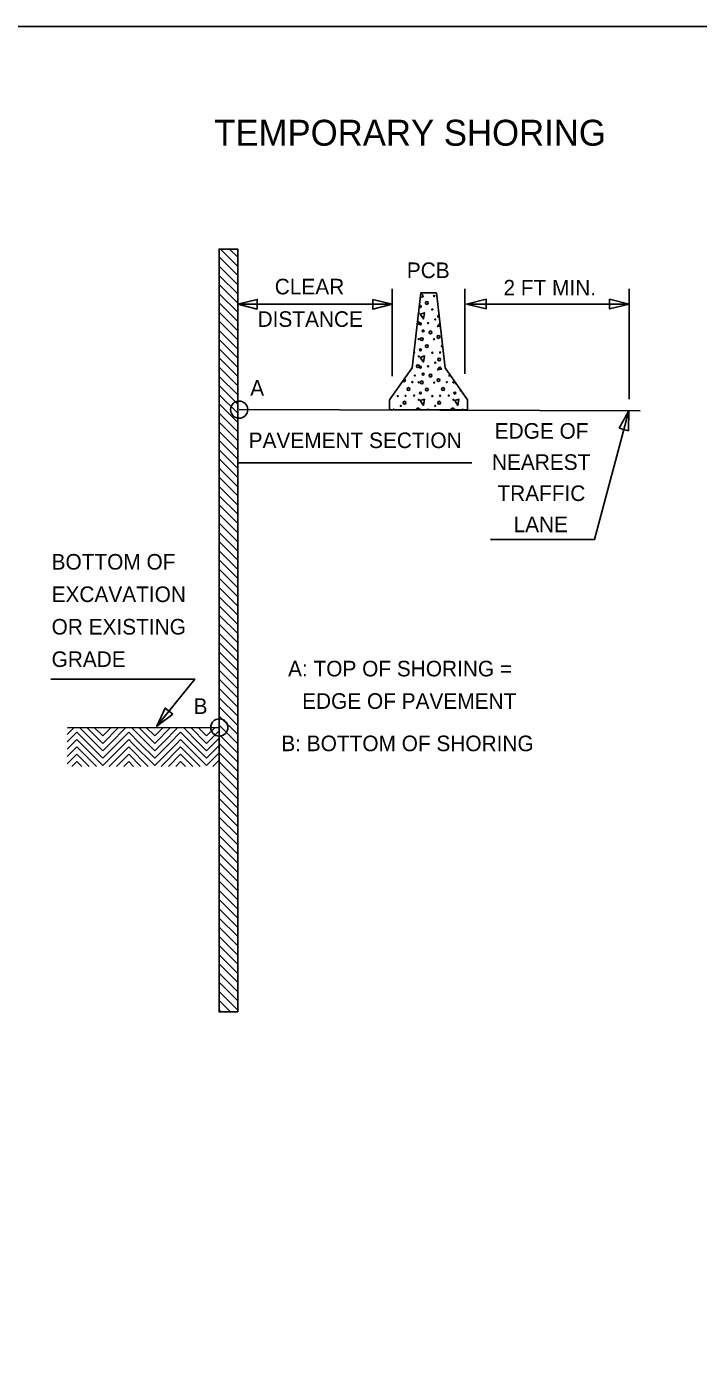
# Model space of a CAD drawing. Extents: x 2487012 to 2497594, y 369516 to 371986.
# Drawn here: x 2487672 to 2487943, y 370720 to 371258 of the extents above; entities that cross this region are included whole.
import ezdxf

# ---------------------------------------------------------------- set-up
doc = ezdxf.new("R2010")
doc.units = 0
for name, color, linetype in [('TC LABEL TEMP SHORING', 7, 'Continuous'), ('TC LABEL TEXT', 7, 'Continuous'), ('TC SHEET LAYOUT SHAPE', 7, 'Continuous')]:
    doc.layers.add(name, color=color, linetype=linetype)

msp = doc.modelspace()

# ---------------------------------------------------------------- linework, layer by layer
at = {"layer": 'TC LABEL TEMP SHORING'}
for p, q in [((2487757.21, 371161.32), (2487750.23, 371168.3)), ((2487757.21, 371165.03), (2487753.94, 371168.3)), ((2487757.21, 371157.61), (2487749.68, 371165.13)), ((2487757.21, 371153.89), (2487749.68, 371161.42)), ((2487757.21, 371150.18), (2487749.68, 371157.71)), ((2487757.21, 371146.47), (2487749.68, 371154)), ((2487757.21, 371142.76), (2487749.68, 371150.28)), ((2487819.64, 371117), (2487819.64, 371152.28)), ((2487849.06, 371117.94), (2487849.06, 371152.28)), ((2487915.46, 371107.65), (2487915.46, 371152.28)), ((2487757.21, 371139.04), (2487749.68, 371146.57)), ((2487757.21, 371135.33), (2487749.68, 371142.86)), ((2487757.21, 371131.62), (2487749.68, 371139.15)), ((2487757.21, 371127.91), (2487749.68, 371135.43)), ((2487838.99, 371138.15), (2487838.94, 371138.21)), ((2487757.21, 371124.19), (2487749.68, 371131.72)), ((2487757.21, 371120.48), (2487749.68, 371128.01)), ((2487757.21, 371116.77), (2487749.68, 371124.3)), ((2487757.21, 371113.06), (2487749.68, 371120.59)), ((2487757.21, 371109.35), (2487749.68, 371116.87)), ((2487757.21, 371105.63), (2487749.68, 371113.16)), ((2487757.21, 371101.92), (2487749.68, 371109.45)), ((2487818.64, 371107.25), (2487818.68, 371107.47)), ((2487757.21, 371098.21), (2487749.68, 371105.74)), ((2487757.21, 371094.5), (2487749.68, 371102.02)), ((2487919.88, 371102.9), (2487757.8, 371103.41)), ((2487757.21, 371090.78), (2487749.68, 371098.31)), ((2487757.21, 371087.07), (2487749.68, 371094.6)), ((2487757.21, 371083.36), (2487749.68, 371090.89)), ((2487757.21, 371079.65), (2487749.68, 371087.17)), ((2487757.21, 371075.93), (2487749.68, 371083.46)), ((2487757.46, 371081.86), (2487851.89, 371081.86)), ((2487757.21, 371072.22), (2487749.68, 371079.75)), ((2487757.21, 371068.51), (2487749.68, 371076.04)), ((2487757.21, 371064.8), (2487749.68, 371072.33)), ((2487757.21, 371061.09), (2487749.68, 371068.61)), ((2487757.21, 371057.37), (2487749.68, 371064.9)), ((2487757.21, 371053.66), (2487749.68, 371061.19)), ((2487757.21, 371049.95), (2487749.68, 371057.48)), ((2487757.21, 371046.24), (2487749.68, 371053.76)), ((2487757.21, 371042.52), (2487749.68, 371050.05)), ((2487757.21, 371038.81), (2487749.68, 371046.34)), ((2487757.21, 371035.1), (2487749.68, 371042.63)), ((2487757.21, 371031.39), (2487749.68, 371038.91)), ((2487757.21, 371027.67), (2487749.68, 371035.2)), ((2487757.21, 371023.96), (2487749.68, 371031.49)), ((2487757.21, 371020.25), (2487749.68, 371027.78)), ((2487757.21, 371016.54), (2487749.68, 371024.07)), ((2487757.21, 371012.83), (2487749.68, 371020.35)), ((2487757.21, 371009.11), (2487749.68, 371016.64)), ((2487757.21, 371005.4), (2487749.68, 371012.93)), ((2487757.21, 371001.69), (2487749.68, 371009.22)), ((2487757.21, 370997.98), (2487749.68, 371005.5)), ((2487757.21, 370994.26), (2487749.68, 371001.79)), ((2487757.21, 370990.55), (2487749.68, 370998.08)), ((2487757.21, 370986.84), (2487749.68, 370994.37)), ((2487757.21, 370983.13), (2487749.68, 370990.65)), ((2487757.21, 370979.41), (2487749.68, 370986.94)), ((2487757.21, 370975.7), (2487749.68, 370983.23)), ((2487757.21, 370971.99), (2487749.68, 370979.52)), ((2487688.25, 370972.11), (2487691.05, 370974.91)), ((2487688.25, 370969.14), (2487692.15, 370973.04)), ((2487688.34, 370974.74), (2487749.77, 370974.91)), ((2487696.71, 370968.48), (2487692.15, 370973.04)), ((2487699.68, 370968.48), (2487693.24, 370974.91)), ((2487702.65, 370968.48), (2487696.21, 370974.91)), ((2487702.65, 370971.45), (2487699.18, 370974.91)), ((2487702.65, 370968.48), (2487709.08, 370974.91)), ((2487702.65, 370971.45), (2487706.11, 370974.91)), ((2487705.62, 370968.48), (2487712.05, 370974.91)), ((2487708.59, 370968.48), (2487713.15, 370973.04)), ((2487717.71, 370968.48), (2487713.15, 370973.04)), ((2487720.68, 370968.48), (2487714.24, 370974.91)), ((2487723.65, 370968.48), (2487717.21, 370974.91)), ((2487723.65, 370971.45), (2487720.18, 370974.91)), ((2487723.65, 370968.48), (2487730.08, 370974.91)), ((2487723.65, 370971.45), (2487727.11, 370974.91)), ((2487726.62, 370968.48), (2487733.05, 370974.91)), ((2487729.59, 370968.48), (2487734.15, 370973.04)), ((2487738.71, 370968.48), (2487734.15, 370973.04)), ((2487741.68, 370968.48), (2487735.24, 370974.91)), ((2487744.65, 370968.48), (2487738.21, 370974.91)), ((2487744.65, 370971.45), (2487741.18, 370974.91)), ((2487744.65, 370971.45), (2487748.11, 370974.91)), ((2487744.65, 370968.48), (2487749.77, 370973.6)), ((2487757.21, 370968.28), (2487749.68, 370975.81)), ((2487688.25, 370966.17), (2487690.55, 370968.48)), ((2487690.55, 370968.48), (2487692.15, 370970.07)), ((2487693.74, 370968.48), (2487692.15, 370970.07)), ((2487702.65, 370959.57), (2487693.74, 370968.48)), ((2487702.65, 370962.54), (2487696.71, 370968.48)), ((2487702.65, 370965.51), (2487699.68, 370968.48)), ((2487702.65, 370959.57), (2487711.55, 370968.48)), ((2487702.65, 370962.54), (2487708.59, 370968.48)), ((2487702.65, 370965.51), (2487705.62, 370968.48)), ((2487711.55, 370968.48), (2487713.15, 370970.07)), ((2487714.74, 370968.48), (2487713.15, 370970.07)), ((2487723.65, 370959.57), (2487714.74, 370968.48)), ((2487723.65, 370962.54), (2487717.71, 370968.48)), ((2487723.65, 370965.51), (2487720.68, 370968.48)), ((2487723.65, 370959.57), (2487732.55, 370968.48)), ((2487723.65, 370962.54), (2487729.59, 370968.48)), ((2487723.65, 370965.51), (2487726.62, 370968.48)), ((2487732.55, 370968.48), (2487734.15, 370970.07)), ((2487735.74, 370968.48), (2487734.15, 370970.07)), ((2487744.65, 370959.57), (2487735.74, 370968.48)), ((2487744.65, 370962.54), (2487738.71, 370968.48)), ((2487744.65, 370965.51), (2487741.68, 370968.48)), ((2487744.65, 370965.51), (2487747.62, 370968.48)), ((2487744.65, 370962.54), (2487749.77, 370967.66)), ((2487747.62, 370968.48), (2487749.77, 370970.63)), ((2487757.21, 370964.57), (2487749.68, 370972.09)), ((2487757.21, 370960.85), (2487749.68, 370968.38)), ((2487688.25, 370963.2), (2487692.15, 370967.1)), ((2487688.25, 370960.23), (2487692.15, 370964.13)), ((2487700.08, 370959.16), (2487692.15, 370967.1)), ((2487697.11, 370959.16), (2487692.15, 370964.13)), ((2487705.21, 370959.16), (2487713.15, 370967.1)), ((2487708.18, 370959.16), (2487713.15, 370964.13)), ((2487721.08, 370959.16), (2487713.15, 370967.1)), ((2487718.11, 370959.16), (2487713.15, 370964.13)), ((2487726.21, 370959.16), (2487734.15, 370967.1)), ((2487729.18, 370959.16), (2487734.15, 370964.13)), ((2487742.08, 370959.16), (2487734.15, 370967.1)), ((2487739.11, 370959.16), (2487734.15, 370964.13)), ((2487744.65, 370959.57), (2487749.77, 370964.69)), ((2487757.21, 370957.14), (2487749.68, 370964.67)), ((2487690.15, 370959.16), (2487692.15, 370961.16)), ((2487694.14, 370959.16), (2487692.15, 370961.16)), ((2487711.15, 370959.16), (2487713.15, 370961.16)), ((2487715.14, 370959.16), (2487713.15, 370961.16)), ((2487732.15, 370959.16), (2487734.15, 370961.16)), ((2487736.14, 370959.16), (2487734.15, 370961.16)), ((2487747.21, 370959.16), (2487749.77, 370961.72)), ((2487757.21, 370953.43), (2487749.68, 370960.96)), ((2487757.21, 370949.72), (2487749.68, 370957.24)), ((2487757.21, 370946), (2487749.68, 370953.53)), ((2487757.21, 370942.29), (2487749.68, 370949.82)), ((2487757.21, 370938.58), (2487749.68, 370946.11)), ((2487757.21, 370934.87), (2487749.68, 370942.39)), ((2487757.21, 370931.15), (2487749.68, 370938.68)), ((2487757.21, 370927.44), (2487749.68, 370934.97)), ((2487757.21, 370923.73), (2487749.68, 370931.26)), ((2487757.21, 370920.02), (2487749.68, 370927.55)), ((2487757.21, 370916.31), (2487749.68, 370923.83)), ((2487757.21, 370912.59), (2487749.68, 370920.12)), ((2487757.21, 370908.88), (2487749.68, 370916.41)), ((2487757.21, 370905.17), (2487749.68, 370912.7)), ((2487757.21, 370901.46), (2487749.68, 370908.98)), ((2487757.21, 370897.74), (2487749.68, 370905.27)), ((2487757.21, 370894.03), (2487749.68, 370901.56)), ((2487757.21, 370890.32), (2487749.68, 370897.85)), ((2487757.21, 370886.61), (2487749.68, 370894.13)), ((2487757.21, 370882.89), (2487749.68, 370890.42)), ((2487757.21, 370879.18), (2487749.68, 370886.71)), ((2487757.21, 370875.47), (2487749.68, 370883)), ((2487757.21, 370871.76), (2487749.68, 370879.29)), ((2487757.21, 370868.05), (2487749.68, 370875.57)), ((2487757.21, 370864.33), (2487749.68, 370871.86)), ((2487757.21, 370860.62), (2487749.68, 370868.15)), ((2487754.26, 370859.86), (2487749.68, 370864.44)), ((2487750.55, 370859.86), (2487749.68, 370860.72))]:
    msp.add_line(p, q, dxfattribs=at)
for points in [[(2487757.21, 370859.86), (2487749.68, 370859.86), (2487749.68, 371168.3), (2487757.21, 371168.3)], [(2487818.64, 371103.36), (2487850.15, 371103.36), (2487850.15, 371107.42), (2487841.04, 371120.26), (2487837.56, 371150.61), (2487831.23, 371150.61), (2487827.75, 371120.26), (2487818.64, 371107.42)], [(2487831.05, 371142.05), (2487832.29, 371140.12), (2487832.68, 371142.6)], [(2487831.05, 371124.55), (2487832.29, 371122.62), (2487832.68, 371125.1)], [(2487831.05, 371107.05), (2487832.29, 371105.12), (2487832.68, 371107.6)], [(2487845.03, 371107.05), (2487846.27, 371105.12), (2487846.66, 371107.6)]]:
    msp.add_lwpolyline(points, close=True, dxfattribs=at)
for points in [[(2487838.94, 371138.21), (2487838.01, 371137), (2487839.1, 371137.21)], [(2487838.94, 371120.72), (2487838.01, 371119.5), (2487839.65, 371119.82), (2487838.94, 371120.72)]]:
    msp.add_lwpolyline(points, dxfattribs=at)
for centre, radius in [((2487831.07, 371145.13), 0.386), ((2487833.69, 371146.54), 0.57), ((2487836.65, 371149.35), 0.209), ((2487835.9, 371143.91), 0.209), ((2487837.11, 371139.91), 0.209), ((2487831.07, 371138.13), 0.386), ((2487832.19, 371135.22), 0.386), ((2487834.21, 371138.41), 0.209), ((2487835.19, 371134.66), 0.57), ((2487830.44, 371131.94), 0.209), ((2487831.63, 371131.94), 0.57), ((2487833.69, 371129.04), 0.57), ((2487836.65, 371131.85), 0.209), ((2487838.38, 371132.79), 0.57), ((2487830.44, 371124.92), 0.209), ((2487831.07, 371127.63), 0.386), ((2487835.9, 371126.41), 0.209), ((2487838.66, 371123.7), 0.57), ((2487839.08, 371126.51), 0.209), ((2487830.11, 371121), 0.57), ((2487831.07, 371120.63), 0.386), ((2487832.19, 371117.72), 0.386), ((2487834.21, 371120.91), 0.209), ((2487837.11, 371122.41), 0.209), ((2487827.82, 371114.54), 0.209), ((2487828.85, 371117.16), 0.209), ((2487830.44, 371114.44), 0.209), ((2487831.63, 371114.44), 0.57), ((2487835.19, 371117.16), 0.57), ((2487836.65, 371114.35), 0.209), ((2487838.38, 371115.29), 0.57), ((2487841.8, 371114.54), 0.209), ((2487842.83, 371117.16), 0.209), ((2487844.42, 371114.44), 0.209), ((2487821.91, 371108.91), 0.209), ((2487825.1, 371109.01), 0.209), ((2487826.27, 371111.73), 0.57), ((2487828.57, 371109.1), 0.209), ((2487830.44, 371107.42), 0.209), ((2487831.07, 371110.13), 0.386), ((2487833.69, 371111.54), 0.57), ((2487835.9, 371108.91), 0.209), ((2487839.08, 371109.01), 0.209), ((2487840.25, 371111.73), 0.57), ((2487842.55, 371109.1), 0.209), ((2487844.42, 371107.42), 0.209), ((2487845.05, 371110.13), 0.386), ((2487823.13, 371104.91), 0.209), ((2487824.68, 371106.2), 0.57), ((2487837.11, 371104.91), 0.209), ((2487838.66, 371106.2), 0.57)]:
    msp.add_circle(centre, radius, dxfattribs=at)
for centre, radius, start, end in [((2487831.63, 371149.44), 0.57, 194.2471, 152.6601), ((2487830.44, 371142.41), 0.209, 217.2103, 129.6969), ((2487838.66, 371141.2), 0.57, 98.5132, 274.5796), ((2487830.11, 371138.5), 0.57, 235.0816, 111.8256), ((2487840.25, 371129.23), 0.57, 121.1535, 251.9393), ((2487828.57, 371126.6), 0.209, 237.2669, 109.6402), ((2487824.4, 371115.29), 0.57, 219.9316, 69.3901), ((2487845.61, 371114.44), 0.57, 164.9198, 265.7585), ((2487847.67, 371111.54), 0.57, 165.0914, 265.587), ((2487820.23, 371103.41), 0.209, 347.631, 192.369), ((2487830.11, 371103.5), 0.57, 345.9595, 194.0405), ((2487831.07, 371103.13), 0.386, 37.6227, 142.3773), ((2487834.21, 371103.41), 0.209, 347.631, 192.369), ((2487844.09, 371103.5), 0.57, 345.9595, 194.0405), ((2487845.05, 371103.13), 0.386, 37.6227, 142.3773), ((2487848.19, 371103.41), 0.209, 347.631, 192.369)]:
    msp.add_arc(centre, radius, start, end, dxfattribs=at)
at = {"layer": 'TC LABEL TEXT'}
msp.add_line((2487849.79, 371146.09), (2487915.43, 371146.09), dxfattribs=at)
for points in [[(2487765.1, 371144.03), (2487757.22, 371146), (2487765.1, 371147.97)], [(2487765.1, 371144.03), (2487757.22, 371146), (2487765.1, 371147.97)], [(2487765.1, 371144.03), (2487757.22, 371146), (2487765.1, 371147.97)], [(2487765.1, 371144.03), (2487757.22, 371146), (2487765.1, 371147.97)], [(2487811.86, 371147.97), (2487819.73, 371146), (2487811.86, 371144.03)], [(2487811.86, 371147.97), (2487819.73, 371146), (2487811.86, 371144.03)], [(2487811.86, 371147.97), (2487819.73, 371146), (2487811.86, 371144.03)], [(2487811.86, 371147.97), (2487819.73, 371146), (2487811.86, 371144.03)], [(2487857.67, 371144.12), (2487849.79, 371146.09), (2487857.67, 371148.06)], [(2487857.67, 371144.12), (2487849.79, 371146.09), (2487857.67, 371148.06)], [(2487857.67, 371144.12), (2487849.79, 371146.09), (2487857.67, 371148.06)], [(2487857.67, 371144.12), (2487849.79, 371146.09), (2487857.67, 371148.06)], [(2487907.55, 371148.06), (2487915.43, 371146.09), (2487907.55, 371144.12)], [(2487907.55, 371148.06), (2487915.43, 371146.09), (2487907.55, 371144.12)], [(2487907.55, 371148.06), (2487915.43, 371146.09), (2487907.55, 371144.12)], [(2487907.55, 371148.06), (2487915.43, 371146.09), (2487907.55, 371144.12)], [(2487911.39, 371095.88), (2487915.31, 371102.99), (2487915.2, 371094.87)], [(2487911.39, 371095.88), (2487915.31, 371102.99), (2487915.2, 371094.87)], [(2487911.39, 371095.88), (2487915.31, 371102.99), (2487915.2, 371094.87)], [(2487911.39, 371095.88), (2487915.31, 371102.99), (2487915.2, 371094.87)], [(2487730.96, 370980.27), (2487724.49, 370975.37), (2487727.9, 370982.74)], [(2487730.96, 370980.27), (2487724.49, 370975.37), (2487727.9, 370982.74)], [(2487730.96, 370980.27), (2487724.49, 370975.37), (2487727.9, 370982.74)], [(2487730.96, 370980.27), (2487724.49, 370975.37), (2487727.9, 370982.74)]]:
    msp.add_lwpolyline(points, close=True, dxfattribs=at)
for points in [[(2487757.22, 371146), (2487819.73, 371146)], [(2487859.45, 371050.86), (2487901.48, 371050.86), (2487915.31, 371102.99)], [(2487681.69, 370994.39), (2487739.82, 370994.39), (2487724.49, 370975.37)]]:
    msp.add_lwpolyline(points, dxfattribs=at)
for centre in [(2487757.8, 371103.41), (2487749.77, 370974.91)]:
    msp.add_circle(centre, 3.48, dxfattribs=at)
at = {"layer": 'TC SHEET LAYOUT SHAPE'}
msp.add_lwpolyline([(2487016.56, 370666.84), (2487016.56, 370976.16), (2487016.56, 371248.27), (2487026.56, 371258.27), (2487469.58, 371258.27), (2487940.56, 371258.27), (2488261.56, 371258.27), (2488261.56, 371178.27), (2488346.56, 371178.27), (2488346.56, 371226.27), (2488506.56, 371226.27), (2488506.56, 370891.3), (2488506.56, 370612.1), (2488506.56, 370360.77), (2488151.56, 370360.77), (2488151.56, 370218.27), (2487778.38, 370218.27), (2487608.92, 370218.27), (2487256.14, 370218.27), (2487016.56, 370218.27)], close=True, dxfattribs=at)

# ---------------------------------------------------------------- texts
at = {"layer": 'TC LABEL TEXT'}
for s, height, p in [('TEMPORARY SHORING', 10.5, (2487747.72, 371210.12)), ('PCB', 6.3, (2487825.6, 371156.61)), ('CLEAR', 6.3, (2487772.2, 371150.01)), ('2 FT MIN.', 6.3, (2487864.67, 371149.57)), ('DISTANCE', 6.3, (2487765.25, 371136.88)), ('A', 6.3, (2487762.28, 371109.03)), ('EDGE OF', 6.3, (2487861.14, 371091.66)), ('PAVEMENT SECTION', 6.3, (2487761.64, 371087.86)), ('NEAREST', 6.3, (2487860.01, 371079.06)), ('TRAFFIC ', 6.3, (2487862.22, 371066.46)), ('LANE', 6.3, (2487868.75, 371053.86)), ('BOTTOM OF ', 6.3, (2487681.97, 371038.73)), ('EXCAVATION', 6.3, (2487681.97, 371025.61)), ('OR EXISTING ', 6.3, (2487681.97, 371012.48)), ('GRADE', 6.3, (2487681.97, 370999.36)), ('A: TOP OF SHORING =', 6.3, (2487777.57, 370995.55)), ('   EDGE OF PAVEMENT', 6.3, (2487776.25, 370982.43)), ('B', 6.3, (2487739.4, 370980.36)), ('B: BOTTOM OF SHORING', 6.3, (2487774.85, 370965.31))]:
    msp.add_text(s, height=height, dxfattribs=at).set_placement(p)

doc.saveas('drawing.dxf')
